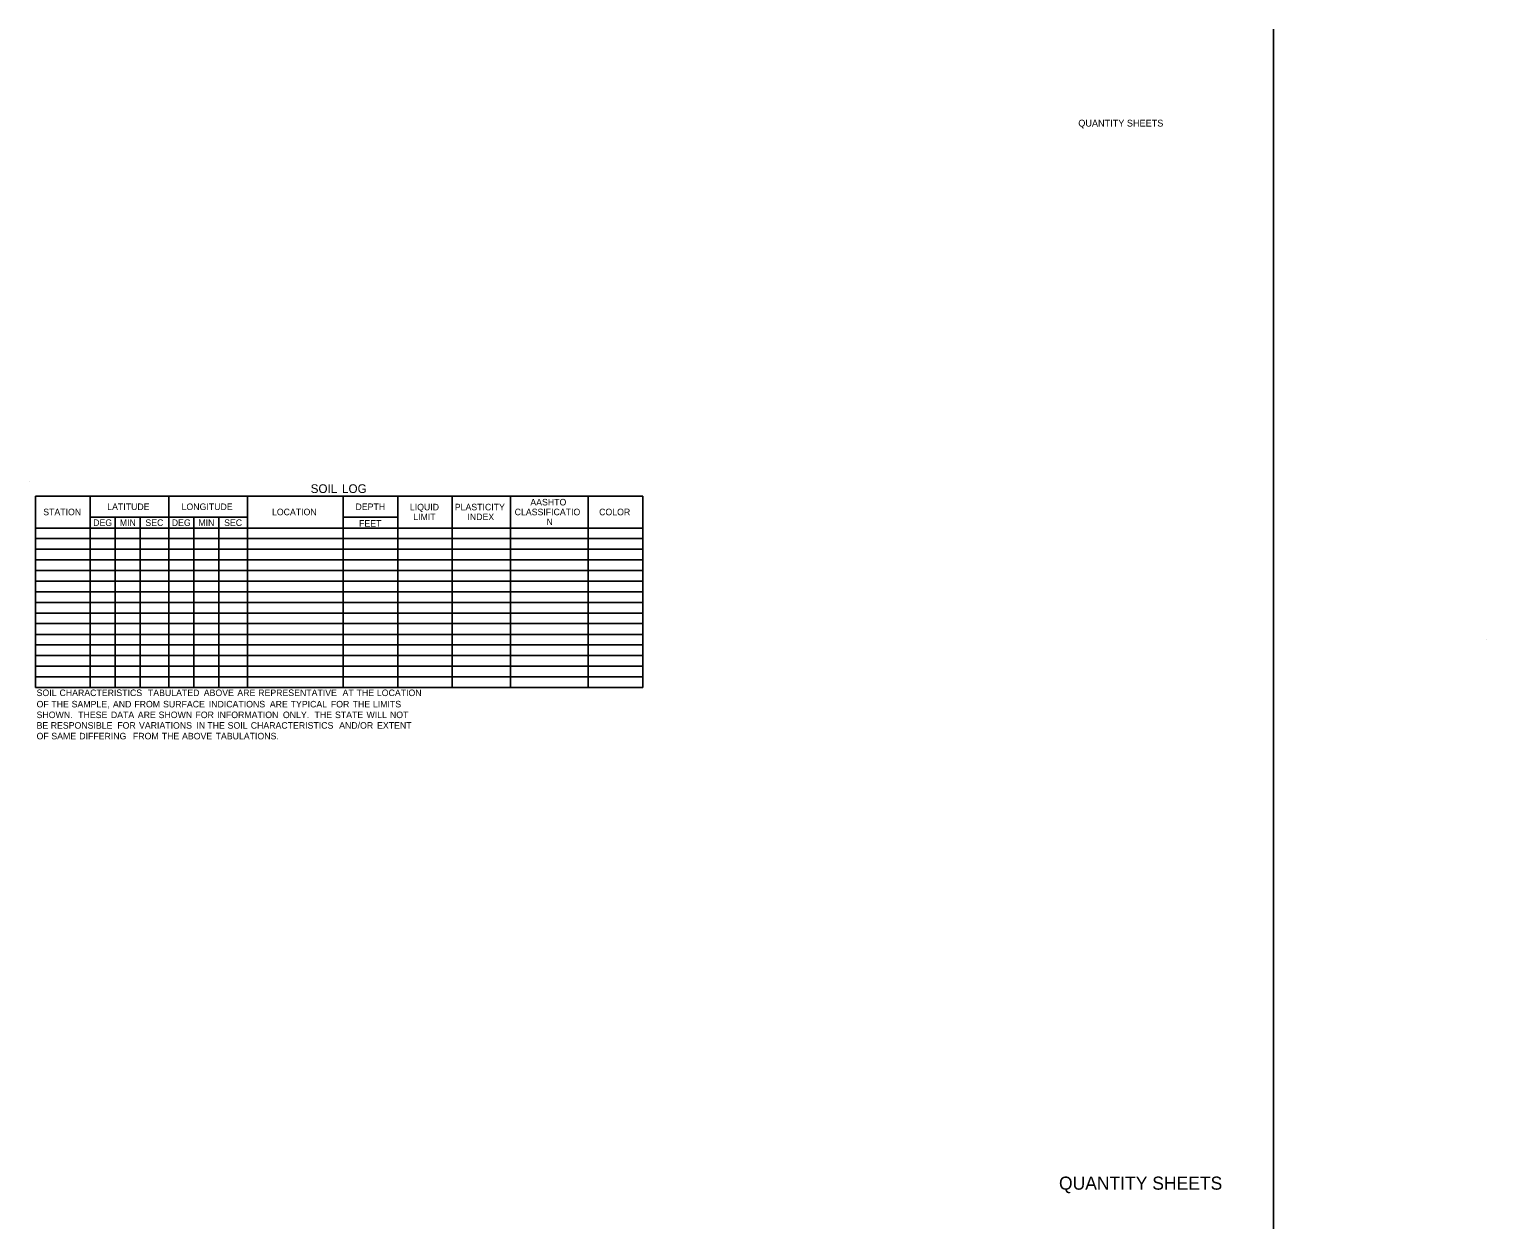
# Model space of a CAD drawing. Extents: x 1955554 to 1962042, y 565952 to 568347.
# Drawn here: x 1955554 to 1956891, y 565952 to 567052 of the extents above; entities that cross this region are included whole.
import ezdxf

# ---------------------------------------------------------------- set-up
doc = ezdxf.new("R2010")
doc.units = 0
for name, color, linetype in [('Default', 7, 'Continuous'), ('R_Border', 7, 'Continuous'), ('STAMP', 7, 'Continuous')]:
    doc.layers.add(name, color=color, linetype=linetype)

msp = doc.modelspace()

# ---------------------------------------------------------------- linework, layer by layer
at = {"layer": 'Default'}
for p, q in [((1955559.9, 566623.5), (1956117.1, 566623.5)), ((1955559.9, 566448), (1955559.9, 566623.5)), ((1955559.9, 566448), (1955559.9, 566623.5)), ((1955610.1, 566448), (1955610.1, 566623.5)), ((1955682.3, 566448), (1955682.3, 566623.5)), ((1955754.4, 566448), (1955754.4, 566623.5)), ((1955842.2, 566448), (1955842.2, 566623.5)), ((1955892.4, 566448), (1955892.4, 566623.5)), ((1955942.1, 566448), (1955942.1, 566623.5)), ((1955995.7, 566448), (1955995.7, 566623.5)), ((1956066.9, 566448), (1956066.9, 566623.5)), ((1956117.1, 566448), (1956117.1, 566623.5)), ((1955610.1, 566604), (1955754.4, 566604)), ((1955633, 566448), (1955633, 566604)), ((1955633, 566448), (1955633, 566604)), ((1955656, 566448), (1955656, 566604)), ((1955656, 566448), (1955656, 566604)), ((1955682.3, 566448), (1955682.3, 566604)), ((1955705.2, 566448), (1955705.2, 566604)), ((1955705.2, 566448), (1955705.2, 566604)), ((1955728.1, 566448), (1955728.1, 566604)), ((1955728.1, 566448), (1955728.1, 566604)), ((1955754.4, 566448), (1955754.4, 566604)), ((1955842.2, 566604), (1955892.4, 566604)), ((1955559.9, 566594.2), (1956117.1, 566594.2)), ((1955559.9, 566584.5), (1956117.1, 566584.5)), ((1955610.1, 566448), (1955610.1, 566594.2)), ((1955754.4, 566594.2), (1955892.4, 566594.2)), ((1955842.2, 566448), (1955842.2, 566594.2)), ((1955892.4, 566594.2), (1956117.1, 566594.2)), ((1955892.4, 566448), (1955892.4, 566594.2)), ((1955942.1, 566448), (1955942.1, 566594.2)), ((1955995.7, 566448), (1955995.7, 566594.2)), ((1956066.9, 566448), (1956066.9, 566594.2)), ((1956117.1, 566574.7), (1956117.1, 566584.5)), ((1955559.9, 566574.7), (1956117.1, 566574.7)), ((1955559.9, 566565), (1956117.1, 566565)), ((1955559.9, 566555.2), (1956117.1, 566555.2)), ((1955559.9, 566545.5), (1956117.1, 566545.5)), ((1955559.9, 566535.7), (1956117.1, 566535.7)), ((1955559.9, 566526), (1956117.1, 566526)), ((1955559.9, 566516.2), (1956117.1, 566516.2)), ((1955559.9, 566506.5), (1956117.1, 566506.5)), ((1955559.9, 566496.7), (1956117.1, 566496.7)), ((1956891.2, 566492.2), (1956891.2, 566492.2)), ((1955559.9, 566487), (1956117.1, 566487)), ((1955559.9, 566477.2), (1956117.1, 566477.2)), ((1955559.9, 566467.5), (1956117.1, 566467.5)), ((1955559.9, 566457.7), (1956117.1, 566457.7)), ((1955559.9, 566448), (1956117.1, 566448))]:
    msp.add_line(p, q, dxfattribs=at)
at = {"layer": 'R_Border'}
for p, q in [((1956695.4, 565951.6), (1956695.4, 567051.6)), ((1955554.1, 566637.1), (1955554.1, 566637.1))]:
    msp.add_line(p, q, dxfattribs=at)

# ---------------------------------------------------------------- texts
at = {"layer": 'Default'}
for s, height, p in [('SOIL', 8, (1955812.3, 566626.3)), (' LOG', 8, (1955838.1, 566626.3)), ('STATION', 6, (1955567, 566605.9)), ('LATITUDE', 6, (1955625.7, 566610.7)), ('LONGITUDE', 6, (1955693.9, 566610.7)), ('LOCATION', 6, (1955776.8, 566605.9)), ('DEPTH', 6, (1955853.4, 566610.7)), ('LIQUID', 6, (1955903.3, 566610.4)), ('PLASTICITY', 6, (1955944.5, 566610.4)), ('CLASSIFICATIO', 6, (1955999.4, 566605.9)), ('AASHTO', 6, (1956013.8, 566614.9)), ('COLOR', 6, (1956076.9, 566605.9)), ('DEG', 6, (1955612.8, 566596.1)), ('MIN', 6, (1955637.2, 566596.1)), ('SEC', 6, (1955660.7, 566596.1)), ('DEG', 6, (1955684.9, 566596.1)), ('MIN', 6, (1955709.3, 566596.1)), ('SEC', 6, (1955732.9, 566596.1)), ('FEET', 6, (1955856.7, 566595.4)), ('LIMIT', 6, (1955906.4, 566601.4)), ('INDEX', 6, (1955956.1, 566601.4)), ('N', 6, (1956028.6, 566596.9)), ('SOIL', 6, (1955560.9, 566440.1)), ('OF', 6, (1955560.9, 566429.7)), (' THE', 6, (1955572.2, 566429.7)), (' CHARACTERISTICS', 6, (1955579.7, 566440.1)), (' SAMPLE,', 6, (1955590.8, 566429.7)), (' AND', 6, (1955628.7, 566429.7)), (' FROM', 6, (1955648.3, 566429.7)), (' TABULATED', 6, (1955660.8, 566440.1)), (' SURFACE', 6, (1955674.7, 566429.7)), (' ABOVE', 6, (1955712, 566440.1)), (' INDICATIONS', 6, (1955716.6, 566429.7)), (' ARE', 6, (1955742.8, 566440.1)), (' REPRESENTATIVE', 6, (1955761.9, 566440.1)), (' ARE', 6, (1955772.6, 566429.7)), (' TYPICAL', 6, (1955791.7, 566429.7)), (' FOR', 6, (1955828.6, 566429.7)), (' AT', 6, (1955839.3, 566440.1)), (' THE', 6, (1955848.6, 566429.7)), (' THE', 6, (1955852.2, 566440.1)), (' LIMITS', 6, (1955867.2, 566429.7)), (' LOCATION', 6, (1955870.8, 566440.1)), ('SHOWN.', 6, (1955560.9, 566419.9)), ('  THESE', 6, (1955594.6, 566419.9)), (' DATA', 6, (1955626.8, 566419.9)), (' ARE', 6, (1955651.5, 566419.9)), (' SHOWN', 6, (1955670.6, 566419.9)), (' FOR', 6, (1955704.4, 566419.9)), (' INFORMATION', 6, (1955724.3, 566419.9)), (' ONLY.', 6, (1955784.6, 566419.9)), ('  THE', 6, (1955811.4, 566419.9)), (' STATE', 6, (1955832.4, 566419.9)), (' WILL', 6, (1955861.3, 566419.9)), (' NOT', 6, (1955882.8, 566419.9)), ('BE', 6, (1955560.9, 566410.2)), (' RESPONSIBLE', 6, (1955571.6, 566410.2)), (' FOR', 6, (1955632.7, 566410.2)), (' VARIATIONS', 6, (1955652.6, 566410.2)), (' IN', 6, (1955705.3, 566410.2)), (' THE', 6, (1955715.3, 566410.2)), (' SOIL', 6, (1955733.9, 566410.2)), (' CHARACTERISTICS', 6, (1955755.1, 566410.2)), (' AND/OR', 6, (1955836.2, 566410.2)), (' EXTENT', 6, (1955871, 566410.2)), ('OF', 6, (1955560.9, 566400.4)), (' SAME', 6, (1955572.2, 566400.4)), (' DIFFERING', 6, (1955597.8, 566400.4)), ('  FROM', 6, (1955644.8, 566400.4)), (' THE', 6, (1955673.5, 566400.4)), (' ABOVE', 6, (1955692.1, 566400.4)), (' TABULATIONS.', 6, (1955722.9, 566400.4))]:
    msp.add_text(s, height=height, dxfattribs=at).set_placement(p)
at = {"layer": 'R_Border'}
msp.add_text('QUANTITY SHEETS', height=12, rotation=0, dxfattribs=at).set_placement((1956498.7, 565987.5))
at = {"layer": 'STAMP'}
msp.add_text('QUANTITY SHEETS', height=6.25, rotation=360, dxfattribs=at).set_placement((1956516.4, 566962.3))

doc.saveas('drawing.dxf')
